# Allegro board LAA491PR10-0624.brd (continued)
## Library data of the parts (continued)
C1-C13 C21-C26 C28-C38 C46-C58 C61-C64 C67-C69 C71 C73 C75-C77 C79-C81 C83 C85 C87-C92 C94-C96 C411 C2326 C2327 C5212 CA21 CA22 CA24 CA25 CA29-CA33 CA38-CA40 CA51 CA54 CA56 CA58 CA60 CA65 CA69 CC14 CC15 CC23 CC25 CC27-CC35 CC40 CD31 CD63 CD64 CE5 CE6 CE11 CE12 CE15 CE18-CE20 CE23 CE24 CE26-CE36 CG1-CG4 CG7-CG11 CI2-CI4 CI7 CI9-CI11 CI13-CI17 CI19 CI22 CI24-CI26 CI30 CI32 CL15 CL19 CL20 CL22 CL26 CL30 CL31 CL34-CL37 CL39 CL41 CL42 CM40 CM44 CM46-CM49 CR1 CR3-CR7 CR9-CR11 CS5 CS6 CS8-CS11 CS13-CS15 CS17 CS105 CS106 CS108 CS109 CV8-CV40 CV43-CV50 CV59-CV76 CV78 CV79 CV81 CV83-CV85 CV87-CV89 CV92-CV95 CV108 CV109 CV112-CV115 CV118 CV119 CV121 CV122 CV124-CV130 CV132 CV133 CV141-CV150 CV152-CV156 CV171-CV174 CV188-CV190 CV193-CV196 CV198 CV199 CV201-CV212 CV216-CV224 CV280 CV281 CV283-CV288 CV290-CV299 CV301-CV308 CV310-CV313 CV315 CV316 CV318 CV319 CV325 CV326 CV328-CV333 CV335 CV349-CV356 CV368-CV401 CX1 CX2 CX4 CX6 CX9-CX11 CX31-CX34 CX37-CX44 CX46 CX47 PC1-PC5 PC7 PC8 PC13-PC16 PC102 PC104 PC108 PC110 PC113 PC114 PC201-PC203 PC207 PC208 PC210 PC300 PC303 PC304 PC307 PC401 PC403 PC404 PC501 PC502 PC504 PC506 PC507 PC509-PC514 PC519-PC523 PC601 PC603 PC604 PC702 PC705 PC708 PC711 PC715 PC717 PC719 PC720 PC722 PC723 PC806 PC809 PC813 PC814 PC816-PC821 PC831 PC832 PC840-PC866 PC869 PC871-PC873 PC1001 PC1003 PC1004 PC1100 PC1101 PC1104 PC1106 PC1200 PC1203 PC1209 PC1214 PC1302 PC1304 PC1306 PC1307 = C_0402
C20 C27 C39-C45 C60 C66 C72 C74 C78 C82 C93 C2305 C2306 C2308 C2309 C2311-C2314 C2316 C2318 C2322-C2324 CA1 CA2 CA23 CA53 CA55 CA57 CA59 CA61-CA64 CA67 CA68 CA71 CA74 CC26 CD59 CD62 CE22 CE25 CG6 CI40 CI43 CI44 CL38 CL43 CL44 CM43 CM45 CR2 CR8 CS16 CV1 CV3-CV7 CV41 CV42 CV77 CV80 CV82 CV86 CV91 CV101-CV103 CV110 CV111 CV116 CV117 CV120 CV123 CV131 CV134 CV136-CV140 CV151 CV170 CV187 CV197 CV200 CV213-CV215 CV322-CV324 CX5 CX35 CX45 PC100 PC103 PC105 PC106 PC109 PC111 PC200 PC204 PC209 PC301 PC302 PC312 PC313 PC503 PC505 PC508 PC701 PC706 PC707 PC709 PC710 PC721 PC803 PC807 PC810 PC811 PC815 PC835 PC867 PC868 PC870 PC1103 PC1105 PC1205 PC1210 PC1212 PC1213 = C_0603
C59 C65 C70 C84 C86 CL33 = C_1206
C2307 C2310 CE16 CG5 CI6 CI12 CI18 CI21 CI23 CI27 CI31 CS7 CS12 CV97 CX3 CX7 CX8 CX36 CX48 PC112 PC115 PC205 PC206 PC211 PC212 PC305 PC306 PC308-PC311 PC400 PC402 PC405 PC517 PC518 PC600 PC602 PC605 PC703 PC704 PC712-PC714 PC716 PC718 PC804 PC805 PC808 PC901-PC923 PC1002 PC1005 PC1102 PC1201 PC1202 PC1204 PC1206 PC1207 PC1211 PC1300 PC1301 PC1303 PC1305 PC1308 = C_0805
CC1-CC11 CC13 CC16-CC22 CC24 = C_0402: room: CPU
CD1-CD11 CD21-CD27 CD30 CD32-CD42 CD52-CD57 CD60 CD61 = C_0402: room: MEMORY
CD12-CD14 CD16-CD20 CD28 CD29 CD43-CD50 CD58 = C_0603: room: MEMORY
CD15 CD51 = C_D2: room: MEMORY
CE1 CE2 = C_0402: room: EDP
CE7-CE9 = C_0402: room: DOCK
CI1 CI8 CI20 PC101 PC107 PC213 PC1108 = C_APXK6R3ARA221MF451
CMOS1 ME1 = SHORTPADS: User Part Number: PART#; room: CPU
CRTF1 = F_1812
CV135 = C_B2
CV327 = C_D2
DA8 = BAT54C-7-F_SOT23-3
DA10 DA12 = AZ5125-02SPR7G_SOT23-3
DC1 = BAT54CW_SOT323-3
DE1 PD101 = L03ESDL5V0CG3-2_SOT-523-3
DE2 = BAT1000-7-F_SOT23-3
DE3-DE5 = PESD5V0U2BT_SOT23-3
DH1 DX1 PD701 = RB751V-40_SOD323-2
DI1 DI4 = IP4292CZ10-TBR_XSON10_2P5X1
DI2 DI5 DI7 = L30ESDL5V0C3-2_SOT23-3
FD1-FD4 = FIDUCIAL_C40M80: room: LED
H2 H4 H5 H8 H9 H12 H16 H17 = H_2P8: room: LED
H6 H10 = H_3P3: room: LED
H7 H18 = H_3P3
H11 = H_2P8
H31-H34 = H_3P7
H35 = H_3P7X3P2N
J9 JP3 JP8 JP9 JP12 PJP203 = JUMP_43X39
J510 J511 J513 JP7 JP13 PJP400 PJP401 PJP600 PJP601 PJP1000 PJP1001 PJP1300 PJP1301 = JUMP_43X79
JCRT1 = C-K_80443B-5K1-152_15P-T
JDB = JESS_UCNR2210M008-0_8P
JDIMM1 JDIMM2 = LCN_DAN06-K4406-0102_204P: room: MEMORY
JFAN = ACES_85204-0300N_3P
JHDD = SANTA_193202-1_22P
JHP = SINGA_2SJ3080-000111F_6P-T
JKB = HB_A823020-SBHR21_30P
JLAN = SANTA_130456-311_8P
JLVDS = STARC_107K40-000001-G2_40P
JMINI = CONCR_525B01BE17A_52P
JODD = SANTA_202801-1_13P
JPWR = HB_A090420-SAHR21_4P
JREAD = T-SOL_143-2300302602_22P_RV
JRTC = LOTES_AAA-BAT-054-K01_2P
JSPK = E-T_3703-Q04N-11R_4P
JTOUCH = ACES_88460-00601-P01_6P
JTP = PS_HPF10052-06M000R_6P
JUSB1 JUSB2 = ACON_TARA4-9K1311_9P: room: ETY-ROOM
JUSB3 = ACON_UARBG-4K1926_4P
JXDP1 = SAMTE_BSH-030-01-L-D-A_60P: room: CPU
L1-L5 = MURAT_LQM2MPN2R2NG0L_2P
L6 L8 L9 = MURAT_BLM18BD102SN1D_L0603_2P
L10-L12 LA3-LA6 PR200 PR206 PR405 PR516 PR519 PR536 PR605 PR709 PR822 PR1101 R3 R4 R23 R245 R2314 R2315 RL19 RL20 RL39 RL40 RV234 RX28 RX29 = R_0603
LA1 = MURAT_BLM15BB221SN1D_2P
LA7-LA10 = KC_FBMA-L10-160808-800LMT_2P
LE1 = KC_FBMA-L11-160808-800LMT_2P: room: EDP
LE2 LV21 LV23 = KC_FBMA-L11-160808-800LMT_2P
LED1 = LED_12-21C-T3D-CM2P1B18X-2C_3P: room: LED
LED2 LED4 = LED_12-21C-T3D-CM2P1B18X-2C_3P
LED3 = LED_HT-210UD5-BP5_3P
LI1 LI3 LI4 LI6 = MURAT_DLW21SN670HQ2L_4P
LI2 LI5 LI7 LI10 LR2 LX6 = KC_WCM-2012HS-900T_4P
LV12-LV16 LV19 LV20 LV22 LV25 LV26 PH1 PH501 PH502 PH800 PR1-PR4 PR6-PR10 PR15-PR18 PR20 PR23 PR24 PR26-PR33 PR102-PR109 PR111 PR114 PR204 PR205 PR207 PR208 PR301 PR304-PR308 PR402-PR404 PR501-PR510 PR512-PR515 PR517 PR518 PR524 PR526 PR528-PR533 PR540 PR602-PR604 PR701 PR703 PR706 PR707 PR711-PR713 PR721 PR723 PR724 PR808 PR813 PR815-PR821 PR824-PR829 PR833-PR840 PR842 PR1001-PR1004 PR1102 PR1105 PR1107 PR1108 PR1110 PR1201-PR1204 PR1208 PR1209 PR1211-PR1214 PR1300-PR1302 PR1304 R1 R2 R6 R10 R12 R13 R15-R22 R24-R42 R159 R250 R252-R256 R286 R2313 R2318 R2329-R2338 R2341 R2346-R2352 R2354-R2359 RA1-RA3 RA5-RA9 RA19 RA51 RA53 RA55 RA56 RA79-RA84 RA130 RA153 RA165 RA166 RA1109 RC10 RC11 RC13 RC21 RC32 RC37 RC56 RC62 RC63 RC65 RC66 RC68 RC75 RC77 RC78 RC89 RC98-RC100 RC105 RC112 RC113 RC123 RC124 RC127-RC132 RC135 RC139 RC362 RD12-RD18 RD45-RD52 RE1-RE3 RE7-RE12 RE18 RE36 RE43 RE47 RE49 RE50 RE60 RE71 RE326 RG1-RG8 RL27 RL31 RL33-RL35 RL37 RL38 RM11 RM13 RM110 RR1-RR3 RS6-RS8 RV1-RV17 RV19-RV49 RV64 RV66-RV71 RV73-RV76 RV81-RV85 RV89-RV91 RV93 RV95-RV98 RV105 RV107-RV109 RV122 RV123 RV125 RV127 RV133 RV136-RV149 RV162 RV163 RV169 RV171 RV181 RV183-RV186 RV191-RV199 RV201-RV204 RV206 RV207 RV215 RV235-RV247 RV250-RV252 RX1-RX3 RX5 RX6 RX8 RX9 RX18 RX21-RX26 RX30 RX31 RX33 RX35-RX53 RX168-RX171 = R_0402
LV17 LV18 = CHENG_MBK1608121YZF_2P
LX1 LX7 LX8 = KC_FBMA-L11-201209-221LMA30_2P
LX9 = CYNTE_PG031B-4R7MS_2P
PBATT = SUYIN_200028MR009G502ZL_9P
PC515 PC516 PC724 = C_EEEFZ1E101P
PC836-PC839 = C_D1
PD1 = IP4223CZ6_SO6
PD2 PD3 = TVNST52302AB0_SOT523-3
PJP100-PJP103 PJP200 PJP201 PJP300 PJP1100 PJP1101 PJP1200 = JUMP_43X118
PJPDC = ACES_50299-00501-003_5P
PL1 PL2 PL4 = CHT_C8BBPH853025_2P
PL3 = CHENG_SMB3025500YA_2P
PL100 PL101 PL1300 = VISHAY_IHLP-2525CZ-01_2P
PL102 PL702 = CYNTE_PCMB053T-1R0MS_2P
PL200 = TAI-T_VMPI0703AR-1R0M-Z01_2P
PL201 PL302 PL501 PL800 PL1201 = L_1812-1806
PL301 PL1200 = CYNTE_PCMB063T-1R0MS_2P
PL400 PL600 = TAIYO_NRS4018T1R0NDGJ_2P
PL502 = TOKO_FDUE1040J-H-R36M-P3_4P
PL701 = TOKO_FDVE1040-H-2R2M-P3_2P
PL802 = MAG_MMD-12CE-R36M-M1L_2P
PL1100 = TAI-T_HCB2012KF-121T50_2P
PL1101 = PANAS_ETQP3W2R2WFN_2P
PQ1-PQ3 = 2N7002DW-T-R7_SOT363-6
PQ4 PQ706 PQ708 = SSM3K7002FU_SC70-3
PQ5 = RHU002N06_SOT323-3
PQ6 = FDV301N_NL_SOT23-3
PQ101-PQ104 PQ200 PQ201 PQ1100 PQ1101 = SIS412DN-T1-GE3_POWERPAK8-5
PQ701 = CSD87312Q3E_SON8-4
PQ702 = AO4407AL_SO8
PQ703 PQ704 = MDU1516URH_POWERDFN56-8-5
PQ705 = MDU1511RH_POWERDFN56-8-5
PQ800 PQ803 = SIR472DP-T1-GE3_POWERPAK8-5
PQ801 PQ802 = SIR818DP-T1_POWERPAK-SO8-5
PQ1201 = 2N7002W-T-R7_SOT323-3
PR5 PR112 PR113 PR203 PR302 PR534 PR705 PR720 PR722 PR805 PR1104 PR1207 PR1303 RE4 = R_1206
PR100 PR101 PR201 PR202 PR300 PR401 PR522 PR535 PR601 PR704 PR708 PR710 PR714 PR715 PR717 PR803 PR804 PR806 PR807 PR809-PR812 PR830 PR845 PR846 PR1103 PR1206 PR1210 R248 R251 R257 R265 R416 RA4 RC57 RC59 RC141 RE37 RE44 RV118-RV121 RV124 RV126 RV248 RX7 RX19 RX20 = R0402_0OHM
PR303 PR802 PR814 PR823 PR1200 R264 RA29-RA32 RC126 RV54 RV59 RX27 = R0603_0OHM
PR702 PR716 = R_1206_4P-D
PU100 = TPS51225CRUKR_QFN20_3X3
PU200 = RT8207MZQW_WQFN20_3X3
PU300 PU1200 = SY8206DQNC_QFN10_3X3
PU400 PU600 = SY8003DFC_DFN8_2X2
PU501 = TPS51622RSM_QFN32_4X4
PU502 = CSD97374CQ4M_SON8_3P5X4P5-S
PU701 = BQ24738RGRR_QFN20_3P5X3P5
PU800 = ISL62881HRZ-T_QFN28_4X4
PU1000 = APL5930KAI-TRG_SO8
PU1100 = TPS51212DSCR_SON10_3X3
PU1300 = SY8036DBC_DFN10_3X3
Q1 Q3 Q4 Q8 Q2307 Q2308 QC3 QD18-QD20 QM30 QV24 QV25 QV28 = 2N7002K_SOT23-3
Q2 QA5 QA6 QH1 QV14 QV15 QX6 = DMN66D0LDW-7_SOT363-6
Q25 = DMG2301U-7_SOT23-3
QC1 = DMN66D0LDW-7_SOT363-6: room: CPU
QD2 = BSS138-G_SOT23-3
QS2 = SI3456BDV-T1-E3_TSOP6
QS3 QX1 = 2N7002KW_SOT323-3
QV22 = AP2301GN-HF_SOT23-3
QX2 = SI3457CDV-T1-GE3_TSOP6
R267 RM25 RM26 RX4 = R0805_0OHM
RC1-RC9 RC12 RC14-RC20 RC22-RC25 RC27-RC29 RC31 RC34-RC36 RC48-RC52 RC58 RC60 RC64 RC67 RC69-RC74 RC76 RC84 RC87 RC88 RC90 RC91 RC97 RC101 RC102 RC104 RC106-RC108 RC110 RC111 RC116 RC118-RC122 RC125 RC133 RC134 RC138 RC140 RC163 = R_0402: room: CPU
RC26 RC33 RC41-RC46 RC81 = R0402_0OHM: room: CPU
RD1 RD4 RD5 RD8 RD10 = R0402_0OHM: room: MEMORY
RD3 RD6 RD7 = R_0402: room: MEMORY
RE5 = R_0402: room: DOCK
RP1 RP36 RP37 RP39-RP57 RP60 = RP_0804_8P4R
RV103 = R_0805
SW1 SW2 = SW_SMT1-05-A_4P
T1 T2 T38-T51 T53 T55 T56 T58 T59 T78-T91 T95 T96 T102 T103 T105 T111-T114 T116 T117 T119 T120 T124-T127 T129-T186 = TPC12
T94 = TPC12: room: LOM
T97-T99 T104 T106 T107 T115 T118 T121 = TPC12: room: SIO
T128 = TPC12: room: KBC
TL2 = TAIMA_IH-115-F_24P
U1 U2 = P_M74VHC1GT125DF2G_SC70_5P
U4 = IT6511FN_QFN56_7X7
U2301 U2304 = TPS22966DPUR_SON14_2X3
U2302 = W25Q64FVSSIG_SO8
U2303 = 74AUP1G07GW_TSSOP5
UA1 = ALC3221-CG_MQFN48_6X6
UC1 = HASWELL-MCP-E-ULT_BGA_1168P-T: room: CPU
UC3 = MC74VHC1G08DFT2G_SC70-5: room: CPU
UC4 = 74CBTLV3126BQ_DHVQFN14_2P5X3: room: CPU
UD1 UV13 UX2 = MC74VHC1G08DFT2G_SC70-5
UE1 = KB9012QF-A2_LQFP128_14X14
UE2 = SN74LVC1G06DCKR_SC70-5
UE3 = G993P1UF_SOP8
UG1 = SLG3NB274VTR_TQFN16_2X3
UI2-UI5 = AP2301MPG-13_MSOP8
UL1 = RTL8106E-CG_QFN32_4X4
UL2 UX1 = APL3512ABI-TRG_SOT23-5
UR1 = RTS5179-GR_QFN24_4X4
UV1 = 2160809000A11SEYMOU_FCBGA_962P
UV3-UV10 = K4G20325FC-HC05_FBGA_170P
UV14 = ADM1032ARMZ-2REEL_MSOP8
UX4 = RTD2136R-CG_QFN48_6X6
X1 = Y_7V27000050_4P
YC1 = Y_Q13FC1350000_2P: room: CPU
YC2 = Y_X3G024000DC1H_4P: room: CPU
YG1 YL2 = Y_FSX3M-25PM20FDO_4P
YV1 = Y_7V27000011_4P

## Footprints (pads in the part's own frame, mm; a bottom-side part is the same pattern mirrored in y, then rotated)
2N7002DW-T-R7_SOT363-6
  oval 0.381x1.397 smd: 1(0,0) 2(0.65,0) 3(1.3,0) 4(1.3,1.725) 5(0.65,1.725) 6(0,1.725)
2N7002K_SOT23-3
  oval 1.016x1.524 smd: 1(0,0) 2(0.965,2.083) 3(-0.965,2.083)
2N7002KW_SOT323-3
  oval 0.813x0.914 smd: 1(0,0) 2(0.65,1.6) 3(-0.65,1.6)
2N7002W-T-R7_SOT323-3
  oval 0.813x0.914 smd: 1(0,0) 2(0.65,1.6) 3(-0.65,1.6)
74AUP1G07GW_TSSOP5
  oval 0.381x1.346 smd: 1(0,0) 2(0.65,0) 3(1.3,0) 4(1.3,1.79) 5(0,1.79)
74CBTLV3126BQ_DHVQFN14_2P5X3
  oval 1.041x0.254 smd: 1(0,0) 7(2.95,0) 8(2.95,0.5) 14(0,0.5)
  oval 0.254x1.041 smd: 2(0.475,-0.975) 3(0.975,-0.975) 4(1.475,-0.975) 5(1.975,-0.975) 6(2.475,-0.975) 9(2.475,1.475) 10(1.975,1.475) 11(1.475,1.475) 12(0.975,1.475) 13(0.475,1.475)
  rect 1.499x0.991 smd: 15(1.475,0.25)
2160809000A11SEYMOU_FCBGA_962P
  round 0.508 smd: A3(0.8,0) A37(26.8,0) A39(27.6,0) AA9(4.8,-15) AA10(5.6,-15) AA11(6.4,-14.4) AA12(7.4,-14.4) AA13(8.4,-14.4) AA15(9.4,-14.4) AA16(10.4,-14.4) AA17(11.4,-14.4) AA18(12.4,-14.4) AA20(13.4,-14.4) AA21(14.4,-14.4) AA22(15.4,-14.4) AA23(16.4,-14.4) AA24(17.4,-14.4) AA26(18.4,-14.4) AA27(19.4,-14.4) AA28(20.4,-14.4) AA29(21.2,-15) AA30(22,-15) AA31(22.8,-15) AB11(6.4,-15.4) AB12(7.4,-15.4) AB13(8.4,-15.4) AB15(9.4,-15.4) AB16(10.4,-15.4) AB17(11.4,-15.4) AB18(12.4,-15.4) AB20(13.4,-15.4) AB21(14.4,-15.4) AB22(15.4,-15.4) AB23(16.4,-15.4) AB24(17.4,-15.4) AB26(18.4,-15.4) AB27(19.4,-15.4) AB28(20.4,-15.4) AC10(5.6,-16.2) AC11(6.4,-16.4) AC12(7.4,-16.4) AC13(8.4,-16.4) AC15(9.4,-16.4) AC16(10.4,-16.4) AC17(11.4,-16.4) AC18(12.4,-16.4) AC20(13.4,-16.4) AC21(14.4,-16.4) AC22(15.4,-16.4) AC23(16.4,-16.4) AC24(17.4,-16.4) AC26(18.4,-16.4) AC27(19.4,-16.4) AC28(20.4,-16.4) AC29(21.2,-16.2) AC30(22,-16.2) AD11(6.4,-17.4) AD12(7.4,-17.4) AD13(8.4,-17.4) AD15(9.4,-17.4) AD16(10.4,-17.4) AD17(11.4,-17.4) AD18(12.4,-17.4) AD20(13.4,-17.4) AD21(14.4,-17.4) AD22(15.4,-17.4) AD23(16.4,-17.4) AD24(17.4,-17.4) AD26(18.4,-17.4) AD27(19.4,-17.4) AD28(20.4,-17.4) AD29(21.2,-17.4) AF12(7.4,-18.4) AF13(8.4,-18.4) AF15(9.4,-18.4) AF16(10.4,-18.4) AF17(11.4,-18.4) AF18(12.4,-18.4) AF20(13.4,-18.4) AF21(14.4,-18.4) AF22(15.4,-18.4) AF23(16.4,-18.4) AF24(17.4,-18.4) AF26(18.4,-18.4) AF27(19.4,-18.4) AF28(20.4,-18.4) AG13(8.4,-19.4) AG15(9.4,-19.4) AG16(10.4,-19.4) AG17(11.4,-19.4) AG18(12.4,-19.4) AG20(13.4,-19.4) AG21(14.4,-19.4) AG22(15.4,-19.4) AG23(16.4,-19.4) AG24(17.4,-19.4) AG26(18.4,-19.4) AG27(19.4,-19.4) AH15(9.4,-20.4) AH16(10.4,-20.4) AH17(11.4,-20.4) AH18(12.4,-20.4) AH20(13.4,-20.4) AH21(14.4,-20.4) AH22(15.4,-20.4) AH23(16.4,-20.4) AH24(17.4,-20.4) AH26(18.4,-20.4) AJ16(10.2,-21.2) AJ17(11.4,-21.2) AJ19(12.6,-21.2) AJ20(13.8,-21.2) AJ21(15,-21.2) AJ23(16.2,-21.2) AJ24(17.4,-21.2) AK17(11.4,-22) AK19(12.6,-22) AK20(13.8,-22) AK21(15,-22) AK23(16.2,-22) AL19(12.6,-22.8) AL20(13.8,-22.8) AL21(15,-22.8) AM20(13.8,-23.6) AU1(0,-26.8) AU3(0.8,-26.8) AU37(26.8,-26.8) AU39(27.6,-26.8) AW1(0,-27.6) AW3(0.8,-27.6) AW37(26.8,-27.6) AW39(27.6,-27.6) C1(0,-0.8) C3(0.8,-0.8) C37(26.8,-0.8) C39(27.6,-0.8) H20(13.8,-4) J19(12.6,-4.8) J20(13.8,-4.8) J21(15,-4.8) K17(11.4,-5.6) K19(12.6,-5.6) K20(13.8,-5.6) K21(15,-5.6) K23(16.2,-5.6) L16(10.4,-6.4) L17(11.4,-6.4) L18(12.4,-6.4) L20(13.4,-6.4) L21(14.4,-6.4) L22(15.4,-6.4) L23(16.4,-6.4) L24(17.4,-6.4) M15(9.4,-7.4) M16(10.4,-7.4) M17(11.4,-7.4) M18(12.4,-7.4) M20(13.4,-7.4) M21(14.4,-7.4) M22(15.4,-7.4) M23(16.4,-7.4) M24(17.4,-7.4) M26(18.4,-7.4) N13(8.4,-8.4) N15(9.4,-8.4) N16(10.4,-8.4) N17(11.4,-8.4) N18(12.4,-8.4) N20(13.4,-8.4) N21(14.4,-8.4) N22(15.4,-8.4) N23(16.4,-8.4) N24(17.4,-8.4) N26(18.4,-8.4) N27(19.4,-8.4) R12(7.4,-9.4) R13(8.4,-9.4) R15(9.4,-9.4) R16(10.4,-9.4) R17(11.4,-9.4) R18(12.4,-9.4) R20(13.4,-9.4) R21(14.4,-9.4) R22(15.4,-9.4) R23(16.4,-9.4) R24(17.4,-9.4) R26(18.4,-9.4) R27(19.4,-9.4) R28(20.4,-9.4) T11(6.4,-10.4) T12(7.4,-10.4) T13(8.4,-10.4) T15(9.4,-10.4) T16(10.4,-10.4) T17(11.4,-10.4) T18(12.4,-10.4) T20(13.4,-10.4) T21(14.4,-10.4) T22(15.4,-10.4) T23(16.4,-10.4) T24(17.4,-10.4) T26(18.4,-10.4) T27(19.4,-10.4) T28(20.4,-10.4) T29(21.2,-10.2) U10(5.6,-11.4) U11(6.4,-11.4) U12(7.4,-11.4) U13(8.4,-11.4) U15(9.4,-11.4) U16(10.4,-11.4) U17(11.4,-11.4) U18(12.4,-11.4) U20(13.4,-11.4) U21(14.4,-11.4) U22(15.4,-11.4) U23(16.4,-11.4) U24(17.4,-11.4) U26(18.4,-11.4) U27(19.4,-11.4) U28(20.4,-11.4) U29(21.2,-11.4) U30(22,-11.4) V11(6.4,-12.4) V12(7.4,-12.4) V13(8.4,-12.4) V15(9.4,-12.4) V16(10.4,-12.4) V17(11.4,-12.4) V18(12.4,-12.4) V20(13.4,-12.4) V21(14.4,-12.4) V22(15.4,-12.4) V23(16.4,-12.4) V24(17.4,-12.4) V26(18.4,-12.4) V27(19.4,-12.4) V28(20.4,-12.4) W9(4.8,-12.6) W10(5.6,-12.6) W29(21.2,-12.6) W30(22,-12.6) W31(22.8,-12.6) Y8(4,-13.8) Y9(4.8,-13.8) Y10(5.6,-13.8) Y11(6.4,-13.4) Y12(7.4,-13.4) Y13(8.4,-13.4) Y15(9.4,-13.4) Y16(10.4,-13.4) Y17(11.4,-13.4) Y18(12.4,-13.4) Y20(13.4,-13.4) Y21(14.4,-13.4) Y22(15.4,-13.4) Y23(16.4,-13.4) Y24(17.4,-13.4) Y26(18.4,-13.4) Y27(19.4,-13.4) Y28(20.4,-13.4) Y29(21.2,-13.8) Y30(22,-13.8) Y31(22.8,-13.8) Y32(23.6,-13.8)
  round 0.305 smd: A5(1.7,0) A6(2.6,0) A8(4.2,0) A10(5.8,0) A12(7.4,0) A14(9,0) A16(10.6,0) A18(12.2,0) A20(13.8,0) A22(15.4,0) A24(17,0) A26(18.6,0) A28(20.2,0) A30(21.8,0) A32(23.4,0) A34(25,0) A35(25.9,0) AA2(0.4,-14.6) AA4(1.2,-14.6) AA6(2.4,-14.8) AA34(25.2,-14.8) AA36(26.4,-14.6) AA38(27.2,-14.6) AB1(0,-15.4) AB3(0.8,-15.4) AB5(1.6,-15.4) AB6(2.4,-15.6) AB34(25.2,-15.6) AB35(26,-15.4) AB37(26.8,-15.4) AB39(27.6,-15.4) AC2(0.4,-16.2) AC4(1.2,-16.2) AC6(2.4,-16.4) AC34(25.2,-16.4) AC36(26.4,-16.2) AC38(27.2,-16.2) AD1(0,-17) AD3(0.8,-17) AD5(1.6,-17) AD6(2.4,-17.2) AD34(25.2,-17.2) AD35(26,-17) AD37(26.8,-17) AD39(27.6,-17) AE2(0.4,-17.8) AE4(1.2,-17.8) AE6(2.4,-18) AE34(25.2,-18) AE36(26.4,-17.8) AE38(27.2,-17.8) AF1(0,-18.6) AF3(0.8,-18.6) AF5(1.6,-18.6) AF6(2.4,-18.8) AF34(25.2,-18.8) AF35(26,-18.6) AF37(26.8,-18.6) AF39(27.6,-18.6) AG2(0.4,-19.4) AG4(1.2,-19.4) AG6(2.4,-19.6) AG34(25.2,-19.6) AG36(26.4,-19.4) AG38(27.2,-19.4) AH1(0,-20.2) AH3(0.8,-20.2) AH5(1.6,-20.2) AH6(2.4,-20.4) AH34(25.2,-20.4) AH35(26,-20.2) AH37(26.8,-20.2) AH39(27.6,-20.2) AJ2(0.4,-21) AJ4(1.2,-21) AJ6(2.4,-21.2) AJ34(25.2,-21.2) AJ36(26.4,-21) AJ38(27.2,-21) AK1(0,-21.8) AK3(0.8,-21.8) AK5(1.6,-21.8) AK6(2.4,-22) AK34(25.2,-22) AK35(26,-21.8) AK37(26.8,-21.8) AK39(27.6,-21.8) AL2(0.4,-22.6) AL4(1.2,-22.6) AL6(2.4,-22.8) AL34(25.2,-22.8) AL36(26.4,-22.6) AL38(27.2,-22.6) AM1(0,-23.4) AM3(0.8,-23.4) AM5(1.6,-23.4) AM6(2.4,-23.6) AM34(25.2,-23.6) AM35(26,-23.4) AM37(26.8,-23.4) AM39(27.6,-23.4) AN2(0.4,-24.2) AN4(1.2,-24.2) AN6(2.4,-24.4) AN34(25.2,-24.4) AN36(26.4,-24.2) AN38(27.2,-24.2) AP1(0,-25) AP3(0.8,-25) AP5(1.6,-25) AP6(2.4,-25.2) AP7(3.2,-25.2) AP8(4,-25.2) AP9(4.8,-25.2) AP10(5.6,-25.2) AP11(6.4,-25.2) AP12(7.2,-25.2) AP13(8,-25.2) AP14(8.8,-25.2) AP15(9.6,-25.2) AP16(10.4,-25.2) AP17(11.2,-25.2) AP18(12,-25.2) AP19(12.8,-25.2) AP20(13.8,-25.2) AP21(14.8,-25.2) AP22(15.6,-25.2) AP23(16.4,-25.2) AP24(17.2,-25.2) AP25(18,-25.2) AP26(18.8,-25.2) AP27(19.6,-25.2) AP28(20.4,-25.2) AP29(21.2,-25.2) AP30(22,-25.2) AP31(22.8,-25.2) AP32(23.6,-25.2) AP33(24.4,-25.2) AP34(25.2,-25.2) AP35(26,-25) AP37(26.8,-25) AP39(27.6,-25) AR1(0,-25.9) AR3(0.8,-25.9) AR5(1.7,-25.9) AR6(2.6,-26) AR8(4.2,-26) AR10(5.8,-26) AR12(7.4,-26) AR14(9,-26) AR16(10.6,-26) AR18(12.2,-26) AR20(13.8,-26) AR22(15.4,-26) AR24(17,-26) AR26(18.6,-26) AR28(20.2,-26) AR30(21.8,-26) AR32(23.4,-26) AR34(25,-26) AR35(25.9,-25.9) AR37(26.8,-25.9) AR39(27.6,-25.9) AT7(3.4,-26.4) AT9(5,-26.4) AT11(6.6,-26.4) AT13(8.2,-26.4) AT15(9.8,-26.4) AT17(11.4,-26.4) AT19(13,-26.4) AT21(14.6,-26.4) AT23(16.2,-26.4) AT25(17.8,-26.4) AT27(19.4,-26.4) AT29(21,-26.4) AT31(22.6,-26.4) AT33(24.2,-26.4) AU5(1.7,-26.8) AU6(2.6,-26.8) AU8(4.2,-26.8) AU10(5.8,-26.8) AU12(7.4,-26.8) AU14(9,-26.8) AU16(10.6,-26.8) AU18(12.2,-26.8) AU20(13.8,-26.8) AU22(15.4,-26.8) AU24(17,-26.8) AU26(18.6,-26.8) AU28(20.2,-26.8) AU30(21.8,-26.8) AU32(23.4,-26.8) AU34(25,-26.8) AU35(25.9,-26.8) AV7(3.4,-27.2) AV9(5,-27.2) AV11(6.6,-27.2) AV13(8.2,-27.2) AV15(9.8,-27.2) AV17(11.4,-27.2) AV19(13,-27.2) AV21(14.6,-27.2) AV23(16.2,-27.2) AV25(17.8,-27.2) AV27(19.4,-27.2) AV29(21,-27.2) AV31(22.6,-27.2) AV33(24.2,-27.2) AW5(1.7,-27.6) AW6(2.6,-27.6) AW8(4.2,-27.6) AW10(5.8,-27.6) AW12(7.4,-27.6) AW14(9,-27.6) AW16(10.6,-27.6) AW18(12.2,-27.6) AW20(13.8,-27.6) AW22(15.4,-27.6) AW24(17,-27.6) AW26(18.6,-27.6) AW28(20.2,-27.6) AW30(21.8,-27.6) AW32(23.4,-27.6) AW34(25,-27.6) AW35(25.9,-27.6) B7(3.4,-0.4) B9(5,-0.4) B11(6.6,-0.4) B13(8.2,-0.4) B15(9.8,-0.4) B17(11.4,-0.4) B19(13,-0.4) B21(14.6,-0.4) B23(16.2,-0.4) B25(17.8,-0.4) B27(19.4,-0.4) B29(21,-0.4) B31(22.6,-0.4) B33(24.2,-0.4) C5(1.7,-0.8) C6(2.6,-0.8) C8(4.2,-0.8) C10(5.8,-0.8) C12(7.4,-0.8) C14(9,-0.8) C16(10.6,-0.8) C18(12.2,-0.8) C20(13.8,-0.8) C22(15.4,-0.8) C24(17,-0.8) C26(18.6,-0.8) C28(20.2,-0.8) C30(21.8,-0.8) C32(23.4,-0.8) C34(25,-0.8) C35(25.9,-0.8) D7(3.4,-1.2) D9(5,-1.2) D11(6.6,-1.2) D13(8.2,-1.2) D15(9.8,-1.2) D17(11.4,-1.2) D19(13,-1.2) D21(14.6,-1.2) D23(16.2,-1.2) D25(17.8,-1.2) D27(19.4,-1.2) D29(21,-1.2) D31(22.6,-1.2) D33(24.2,-1.2) E1(0,-1.7) E3(0.8,-1.7) E5(1.7,-1.7) E6(2.6,-1.6) E8(4.2,-1.6) E10(5.8,-1.6) E12(7.4,-1.6) E14(9,-1.6) E16(10.6,-1.6) E18(12.2,-1.6) E20(13.8,-1.6) E22(15.4,-1.6) E24(17,-1.6) E26(18.6,-1.6) E28(20.2,-1.6) E30(21.8,-1.6) E32(23.4,-1.6) E34(25,-1.6) E35(25.9,-1.7) E37(26.8,-1.7) E39(27.6,-1.7) F1(0,-2.6) F3(0.8,-2.6) F5(1.6,-2.6) F6(2.4,-2.4) F7(3.2,-2.4) F8(4,-2.4) F9(4.8,-2.4) F10(5.6,-2.4) F11(6.4,-2.4) F12(7.2,-2.4) F13(8,-2.4) F14(8.8,-2.4) F15(9.6,-2.4) F16(10.4,-2.4) F17(11.2,-2.4) F18(12,-2.4) F19(12.8,-2.4) F20(13.8,-2.4) F21(14.8,-2.4) F22(15.6,-2.4) F23(16.4,-2.4) F24(17.2,-2.4) F25(18,-2.4) F26(18.8,-2.4) F27(19.6,-2.4) F28(20.4,-2.4) F29(21.2,-2.4) F30(22,-2.4) F31(22.8,-2.4) F32(23.6,-2.4) F33(24.4,-2.4) F34(25.2,-2.4) F35(26,-2.6) F37(26.8,-2.6) F39(27.6,-2.6) G2(0.4,-3.4) G4(1.2,-3.4) G6(2.4,-3.2) G34(25.2,-3.2) G36(26.4,-3.4) G38(27.2,-3.4) H1(0,-4.2) H3(0.8,-4.2) H5(1.6,-4.2) H6(2.4,-4) H34(25.2,-4) H35(26,-4.2) H37(26.8,-4.2) H39(27.6,-4.2) J2(0.4,-5) J4(1.2,-5) J6(2.4,-4.8) J34(25.2,-4.8) J36(26.4,-5) J38(27.2,-5) K1(0,-5.8) K3(0.8,-5.8) K5(1.6,-5.8) K6(2.4,-5.6) K34(25.2,-5.6) K35(26,-5.8) K37(26.8,-5.8) K39(27.6,-5.8) L2(0.4,-6.6) L4(1.2,-6.6) L6(2.4,-6.4) L34(25.2,-6.4) L36(26.4,-6.6) L38(27.2,-6.6) M1(0,-7.4) M3(0.8,-7.4) M5(1.6,-7.4) M6(2.4,-7.2) M34(25.2,-7.2) M35(26,-7.4) M37(26.8,-7.4) M39(27.6,-7.4) N2(0.4,-8.2) N4(1.2,-8.2) N6(2.4,-8) N34(25.2,-8) N36(26.4,-8.2) N38(27.2,-8.2) P1(0,-9) P3(0.8,-9) P5(1.6,-9) P6(2.4,-8.8) P34(25.2,-8.8) P35(26,-9) P37(26.8,-9) P39(27.6,-9) R2(0.4,-9.8) R4(1.2,-9.8) R6(2.4,-9.6) R34(25.2,-9.6) R36(26.4,-9.8) R38(27.2,-9.8) T1(0,-10.6) T3(0.8,-10.6) T5(1.6,-10.6) T6(2.4,-10.4) T34(25.2,-10.4) T35(26,-10.6) T37(26.8,-10.6) T39(27.6,-10.6) U2(0.4,-11.4) U4(1.2,-11.4) U6(2.4,-11.2) U34(25.2,-11.2) U36(26.4,-11.4) U38(27.2,-11.4) V1(0,-12.2) V3(0.8,-12.2) V5(1.6,-12.2) V6(2.4,-12) V34(25.2,-12) V35(26,-12.2) V37(26.8,-12.2) V39(27.6,-12.2) W2(0.4,-13) W4(1.2,-13) W6(2.4,-12.8) W34(25.2,-12.8) W36(26.4,-13) W38(27.2,-13) Y1(0,-13.8) Y3(0.8,-13.8) Y5(1.6,-13.8) Y6(2.4,-13.8) Y34(25.2,-13.8) Y35(26,-13.8) Y37(26.8,-13.8) Y39(27.6,-13.8)
  round 0.406 smd: AA7(3.2,-15) AA8(4,-15) AA32(23.6,-15) AA33(24.4,-15) AC7(3.2,-16.2) AC8(4,-16.2) AC9(4.8,-16.2) AC31(22.8,-16.2) AC32(23.6,-16.2) AC33(24.4,-16.2) AD7(3.2,-17.4) AD8(4,-17.4) AD9(4.8,-17.4) AD10(5.6,-17.4) AD30(22,-17.4) AD31(22.8,-17.4) AD32(23.6,-17.4) AD33(24.4,-17.4) AF7(3.2,-18.6) AF8(4,-18.6) AF9(4.8,-18.6) AF10(5.6,-18.6) AF11(6.4,-18.4) AF29(21.2,-18.6) AF30(22,-18.6) AF31(22.8,-18.6) AF32(23.6,-18.6) AF33(24.4,-18.6) AG7(3.2,-19.8) AG8(4,-19.8) AG9(4.8,-19.8) AG10(5.6,-19.8) AG11(6.4,-19.4) AG12(7.4,-19.4) AG28(20.4,-19.4) AG29(21.2,-19.8) AG30(22,-19.8) AG31(22.8,-19.8) AG32(23.6,-19.8) AG33(24.4,-19.8) AH11(6.4,-20.4) AH12(7.4,-20.4) AH13(8.4,-20.4) AH27(19.4,-20.4) AH28(20.4,-20.4) AH29(21.2,-20.6) AJ7(3.2,-21) AJ8(4,-21) AJ9(4.8,-21) AJ10(5.6,-21) AJ11(6.6,-21.2) AJ13(7.8,-21.2) AJ14(9,-21.2) AJ26(18.6,-21.2) AJ27(19.8,-21.2) AJ28(20.6,-21.2) AJ30(22,-21) AJ31(22.8,-21) AJ32(23.6,-21) AJ33(24.4,-21) AK7(3.2,-22) AK8(4,-22) AK9(4.8,-22) AK10(5.6,-22) AK11(6.6,-22) AK13(7.8,-22) AK14(9,-22) AK16(10.2,-22) AK24(17.4,-22) AK26(18.6,-22) AK27(19.8,-22) AK29(21,-22) AK30(22,-22) AK31(22.8,-22) AK32(23.6,-22) AK33(24.4,-22) AL7(3.2,-22.8) AL8(4,-22.8) AL9(4.8,-22.8) AL10(5.6,-22.8) AL11(6.6,-22.8) AL13(7.8,-22.8) AL14(9,-22.8) AL16(10.2,-22.8) AL17(11.4,-22.8) AL23(16.2,-22.8) AL24(17.4,-22.8) AL26(18.6,-22.8) AL27(19.8,-22.8) AL29(21,-22.8) AL30(22,-22.8) AL31(22.8,-22.8) AL32(23.6,-22.8) AL33(24.4,-22.8) AM7(3.2,-23.6) AM8(4,-23.6) AM9(4.8,-23.6) AM10(5.6,-23.6) AM11(6.6,-23.6) AM13(7.8,-23.6) AM14(9,-23.6) AM16(10.2,-23.6) AM17(11.4,-23.6) AM19(12.6,-23.6) AM21(15,-23.6) AM23(16.2,-23.6) AM24(17.4,-23.6) AM26(18.6,-23.6) AM27(19.8,-23.6) AM29(21,-23.6) AM30(22,-23.6) AM31(22.8,-23.6) AM32(23.6,-23.6) AM33(24.4,-23.6) AN7(3.2,-24.4) AN8(4,-24.4) AN9(4.8,-24.4) AN10(5.6,-24.4) AN11(6.6,-24.4) AN13(7.8,-24.4) AN14(9,-24.4) AN16(10.2,-24.4) AN17(11.4,-24.4) AN19(12.6,-24.4) AN20(13.8,-24.4) AN21(15,-24.4) AN23(16.2,-24.4) AN24(17.4,-24.4) AN26(18.6,-24.4) AN27(19.8,-24.4) AN29(21,-24.4) AN30(22,-24.4) AN31(22.8,-24.4) AN32(23.6,-24.4) AN33(24.4,-24.4) G7(3.2,-3.2) G8(4,-3.2) G9(4.8,-3.2) G10(5.6,-3.2) G11(6.6,-3.2) G13(7.8,-3.2) G14(9,-3.2) G16(10.2,-3.2) G17(11.4,-3.2) G19(12.6,-3.2) G20(13.8,-3.2) G21(15,-3.2) G23(16.2,-3.2) G24(17.4,-3.2) G26(18.6,-3.2) G27(19.8,-3.2) G29(21,-3.2) G30(22,-3.2) G31(22.8,-3.2) G32(23.6,-3.2) G33(24.4,-3.2) H7(3.2,-4) H8(4,-4) H9(4.8,-4) H10(5.6,-4) H11(6.6,-4) H13(7.8,-4) H14(9,-4) H16(10.2,-4) H17(11.4,-4) H19(12.6,-4) H21(15,-4) H23(16.2,-4) H24(17.4,-4) H26(18.6,-4) H27(19.8,-4) H29(21,-4) H30(22,-4) H31(22.8,-4) H32(23.6,-4) H33(24.4,-4) J7(3.2,-4.8) J8(4,-4.8) J9(4.8,-4.8) J10(5.6,-4.8) J11(6.6,-4.8) J13(7.8,-4.8) J14(9,-4.8) J16(10.2,-4.8) J17(11.4,-4.8) J23(16.2,-4.8) J24(17.4,-4.8) J26(18.6,-4.8) J27(19.8,-4.8) J29(21,-4.8) J30(22,-4.8) J31(22.8,-4.8) J32(23.6,-4.8) J33(24.4,-4.8) K7(3.2,-5.6) K8(4,-5.6) K9(4.8,-5.6) K10(5.6,-5.6) K11(6.6,-5.6) K13(7.8,-5.6) K14(9,-5.6) K16(10.2,-5.6) K24(17.4,-5.6) K26(18.6,-5.6) K27(19.8,-5.6) K29(21,-5.6) K30(22,-5.6) K31(22.8,-5.6) K32(23.6,-5.6) K33(24.4,-5.6) L7(3.2,-6.6) L8(4,-6.6) L9(4.8,-6.6) L10(5.6,-6.6) L11(6.4,-6.4) L12(7.4,-6.4) L13(8.4,-6.4) L15(9.4,-6.4) L26(18.4,-6.4) L27(19.4,-6.4) L28(20.4,-6.4) L29(21.2,-6.6) L30(22,-6.6) L31(22.8,-6.6) L32(23.6,-6.6) L33(24.4,-6.6) M11(6.4,-7.4) M12(7.4,-7.4) M13(8.4,-7.4) M27(19.4,-7.4) M28(20.4,-7.4) N7(3.2,-7.8) N8(4,-7.8) N9(4.8,-7.8) N10(5.6,-7.8) N11(6.4,-8.4) N12(7.4,-8.4) N28(20.4,-8.4) N29(21.2,-7.8) N30(22,-7.8) N31(22.8,-7.8) N32(23.6,-7.8) N33(24.4,-7.8) P7(3.2,-9) P8(4,-9) P9(4.8,-9) P10(5.6,-9) P29(21.2,-9) P30(22,-9) P31(22.8,-9) P32(23.6,-9) P33(24.4,-9) R11(6.4,-9.4) T7(3.2,-10.2) T8(4,-10.2) T9(4.8,-10.2) T10(5.6,-10.2) T30(22,-10.2) T31(22.8,-10.2) T32(23.6,-10.2) T33(24.4,-10.2) U7(3.2,-11.4) U8(4,-11.4) U9(4.8,-11.4) U31(22.8,-11.4) U32(23.6,-11.4) U33(24.4,-11.4) W7(3.2,-12.6) W8(4,-12.6) W32(23.6,-12.6) W33(24.4,-12.6) Y7(3.2,-13.8) Y33(24.4,-13.8)
ACES_50299-00501-003_5P
  round 1.803 hole 1.803 unplated: (-0.2,5.2) (8.2,5.2)
  oval 0.889x2.388 smd: 1(0,0) 2(2,0) 3(4,0) 4(6,0) 5(8,0)
ACES_85204-0300N_3P
  oval 0.787x1.6 smd: 1(0,0) 2(1.25,0) 3(2.5,0)
  rect 2.108x2.997 smd: 4(-2.55,-2.9) 5(5.05,-2.9)
ACES_88460-00601-P01_6P
  oval 0.508x0.991 smd: 1(0,0) 2(0.8,0) 3(1.6,0) 4(2.4,0) 5(3.2,0) 6(4,0)
  rect 1.194x1.702 smd: 7(-1.3,-1.95) 8(5.3,-1.95)
ACON_TARA4-9K1311_9P
  round 1.194 hole 0.711: 1(0,0) 2(-2.5,0) 3(-4.5,0) 4(-7,0) 5(-7.5,-1.5) 6(-5.5,-1.5) 7(-3.5,-1.5) 8(-1.5,-1.5) 9(0.5,-1.5)
  oval 1.397x2.591 hole 0.787x2.007: 10(-11.35,-1.59) 13(4.35,-1.59)
  oval 1.397x2.388 hole 0.787x1.803: 11(-11.35,-9.09) 12(4.35,-9.09)
ACON_UARBG-4K1926_4P
  round 1.422 hole 0.914: 1(0,0) 2(-2.5,0) 3(-4.5,0) 4(-7,0)
  oval 1.397x2.819 hole 0.889x2.311: 5(-9.9,0) 6(2.9,0)
  oval 1.219x2.108 hole 0.711x1.6: 7(-11.2,-7.45) 8(4.2,-7.45)
ADM1032ARMZ-2REEL_MSOP8
  oval 0.381x1.626 smd: 1(0,0) 2(0.65,0) 3(1.3,0) 4(1.95,0) 5(1.95,4.3) 6(1.3,4.3) 7(0.65,4.3) 8(0,4.3)
ALC3221-CG_MQFN48_6X6
  oval 0.203x1.041 smd: 1(0,0) 2(0.4,0) 3(0.8,0) 4(1.2,0) 5(1.6,0) 6(2,0) 7(2.4,0) 8(2.8,0) 9(3.2,0) 10(3.6,0) 11(4,0) 12(4.4,0) 25(4.4,5.95) 26(4,5.95) 27(3.6,5.95) 28(3.2,5.95) 29(2.8,5.95) 30(2.4,5.95) 31(2,5.95) 32(1.6,5.95) 33(1.2,5.95) 34(0.8,5.95) 35(0.4,5.95) 36(0,5.95)
  oval 1.041x0.203 smd: 13(5.175,0.775) 14(5.175,1.175) 15(5.175,1.575) 16(5.175,1.975) 17(5.175,2.375) 18(5.175,2.775) 19(5.175,3.175) 20(5.175,3.575) 21(5.175,3.975) 22(5.175,4.375) 23(5.175,4.775) 24(5.175,5.175) 37(-0.775,5.175) 38(-0.775,4.775) 39(-0.775,4.375) 40(-0.775,3.975) 41(-0.775,3.575) 42(-0.775,3.175) 43(-0.775,2.775) 44(-0.775,2.375) 45(-0.775,1.975) 46(-0.775,1.575) 47(-0.775,1.175) 48(-0.775,0.775)
  rect 4.394x4.394 smd: 49(2.2,2.975)
AO4407AL_SO8
  oval 0.635x1.854 smd: 1(0,0) 2(1.27,0) 3(2.54,0) 4(3.81,0) 5(3.81,5.165) 6(2.54,5.165) 7(1.27,5.165) 8(0,5.165)
AP2301GN-HF_SOT23-3
  oval 1.016x1.524 smd: 1(0,0) 2(0.965,2.083) 3(-0.965,2.083)
AP2301MPG-13_MSOP8
  oval 0.381x1.626 smd: 1(0,0) 2(0.65,0) 3(1.3,0) 4(1.95,0) 5(1.95,4.3) 6(1.3,4.3) 7(0.65,4.3) 8(0,4.3)
  rect 1.803x1.499 smd: 9(0.975,2.15)
APL3512ABI-TRG_SOT23-5
  oval 0.61x1.041 smd: 1(0,0) 2(0.95,0) 3(1.9,0) 4(1.9,2.7) 5(0,2.7)
APL5930KAI-TRG_SO8
  oval 0.635x1.854 smd: 1(0,0) 2(1.27,0) 3(2.54,0) 4(3.81,0) 5(3.81,5.165) 6(2.54,5.165) 7(1.27,5.165) 8(0,5.165)
  rect 2.87x2.489 smd: 9(1.905,2.582)
AZ5125-02SPR7G_SOT23-3
  oval 1.016x1.524 smd: 1(0,0) 2(0.965,2.083) 3(-0.965,2.083)
BAT54C-7-F_SOT23-3
  oval 1.016x1.524 smd: 1(0,0) 2(0.965,2.083) 3(-0.965,2.083)
BAT54CW_SOT323-3
  oval 0.66x0.864 smd: 1(0,0) 2(-0.65,-1.85) 3(0.65,-1.85)
BAT1000-7-F_SOT23-3
  oval 1.016x1.524 smd: 1(0,0) 2(0.965,2.083) 3(-0.965,2.083)
BQ24738RGRR_QFN20_3P5X3P5
  oval 0.254x1.041 smd: 1(0,0) 2(0.5,0) 3(1,0) 4(1.5,0) 5(2,0) 11(2,3.45) 12(1.5,3.45) 13(1,3.45) 14(0.5,3.45) 15(0,3.45)
  oval 1.041x0.254 smd: 6(2.725,0.725) 7(2.725,1.225) 8(2.725,1.725) 9(2.725,2.225) 10(2.725,2.725) 16(-0.725,2.725) 17(-0.725,2.225) 18(-0.725,1.725) 19(-0.725,1.225) 20(-0.725,0.725)
  rect 2.057x2.057 smd: 21(1,1.725)
BSS138-G_SOT23-3
  oval 1.016x1.524 smd: 1(0,0) 2(0.965,2.083) 3(-0.965,2.083)
C-K_80443B-5K1-152_15P-T
  round 0.965 hole 0.711: 1(0,0) 2(-2.29,0) 3(-4.58,0) 4(-6.87,0) 5(-9.16,0) 6(1.145,0) 7(-1.145,0) 8(-3.435,0) 9(-5.725,0) 10(-8.015,0) 11(0,-1.4) 12(-2.29,-1.4) 13(-4.58,-1.4) 14(-6.87,-1.4) 15(-9.16,-1.4)
  oval 1.092x2.997 hole 0.787x2.692: 16(5.47,0.1) 17(-14.63,0.1)
C_0402
  rect 0.508x0.559 smd: 1(0,0) 2(0.914,0)
C_0603
  rect 0.635x0.889 smd: 1(0,0) 2(1.397,0)
C_0805
  rect 0.813x1.397 smd: 1(0,0) 2(1.702,0)
C_1206
  rect 1.016x1.651 smd: 1(0,0) 2(2.667,0)
C_APXK6R3ARA221MF451
  oval 3.15x1.6 smd: 1(0,0) 2(5.05,0)
C_B2
  rect 1.346x2.692 smd: 1(0,0) 2(-2.75,0)
C_D1
  rect 1.803x2.794 smd: 1(0,0) 2(6.5,0)
C_D2
  rect 2.388x2.794 smd: 1(0,0) 2(6.4,0)
C_EEEFZ1E101P
  oval 3.2x1.6 smd: 1(0,0) 2(5,0)
CHENG_MBK1608121YZF_2P
  rect 0.991x0.787 smd: 1(0,0) 2(1.6,0)
CHENG_SMB3025500YA_2P
  rect 2.997x1.803 smd: 1(0,0) 2(4,0)
CHT_C8BBPH853025_2P
  rect 2.54x1.397 smd: 1(-3.81,0) 2(3.81,0)
CONCR_525B01BE17A_52P
  round 1.6 hole 1.6 unplated: (-5.075,-4.85) (28.675,-4.85)
  oval 0.61x1.473 hole 0.406x0.711: 1(0,0) 3(0.8,0) 5(1.6,0) 7(2.4,0) 9(3.2,0) 11(4,0) 13(4.8,0) 15(5.6,0) 17(9.6,0) 19(10.4,0) 21(11.2,0) 23(12,0) 25(12.8,0) 27(13.6,0) 29(14.4,0) 31(15.2,0) 33(16,0) 35(16.8,0) 37(17.6,0) 39(18.4,0) 41(19.2,0) 43(20,0) 45(20.8,0) 47(21.6,0) 49(22.4,0) 51(23.2,0)
  oval 0.61x2.007 smd: 2(0.4,2.5) 4(1.2,2.5) 6(2,2.5) 8(2.8,2.5) 10(3.6,2.5) 12(4.4,2.5) 14(5.2,2.5) 16(6,2.5) 18(10,2.5) 20(10.8,2.5) 22(11.6,2.5) 24(12.4,2.5) 26(13.2,2.5) 28(14,2.5) 30(14.8,2.5) 32(15.6,2.5) 34(16.4,2.5) 36(17.2,2.5) 38(18,2.5) 40(18.8,2.5) 42(19.6,2.5) 44(20.4,2.5) 46(21.2,2.5) 48(22,2.5) 50(22.8,2.5) 52(23.6,2.5)
  oval 1.549x2.769 hole 0.787x2.007: 53(28.675,-7.65) 54(-5.075,-7.65)
CSD87312Q3E_SON8-4
  rect 2.388x0.66 smd: 1(0,0)
  rect 0.432x0.66 smd: 2(0.975,2.95)
  rect 1.753x0.66 smd: 3(-0.325,2.95)
  custom 0.475x0.475 smd: 4(0,1.475)
CSD97374CQ4M_SON8_3P5X4P5-S
  oval 0.203x0.914 smd: 1(0,0) 2(0.4,0) 3(0.8,0) 6(0.8,3.505) 7(0.4,3.505) 8(0,3.505)
  custom 0.225x0.225 smd: 4(2.2,0.265) 5(2.2,3.24)
  rect 4.039x2.21 smd: 9(1.6,1.752)
CYNTE_PCMB053T-1R0MS_2P
  rect 1.905x2.794 smd: 1(0,0) 2(4.1,0)
CYNTE_PCMB063T-1R0MS_2P
  rect 2.159x3.505 smd: 1(0,0) 2(5.85,0)
CYNTE_PG031B-4R7MS_2P
  rect 0.889x1.194 smd: 1(0,0) 2(2.2,0)
DMG2301U-7_SOT23-3
  oval 1.016x1.524 smd: 1(0,0) 2(0.965,2.083) 3(-0.965,2.083)
DMN66D0LDW-7_SOT363-6
  oval 0.432x0.61 smd: 1(0,0) 2(0.65,0) 3(1.3,0) 4(1.3,1.9) 5(0.65,1.9) 6(0,1.9)
E-T_3703-Q04N-11R_4P
  oval 0.61x1.549 smd: 1(0,0) 2(1,0) 3(2,0) 4(3,0)
  rect 1.194x2.007 smd: 5(4.3,-3.775) 6(-1.3,-3.775)
F_1812
  rect 1.245x3.658 smd: 1(-2.07,0) 2(2.07,0)
FDV301N_NL_SOT23-3
  oval 1.016x1.524 smd: 1(0,0) 2(0.965,2.083) 3(-0.965,2.083)
FIDUCIAL_C40M80
  round 1.016 smd: 1(0,0)
G993P1UF_SOP8
  oval 0.635x1.854 smd: 1(0,0) 2(1.27,0) 3(2.54,0) 4(3.81,0) 5(3.81,5.165) 6(2.54,5.165) 7(1.27,5.165) 8(0,5.165)
H_2P8
  round 3.302 hole 2.794: 1(0,0)
H_3P3
  round 3.81 hole 3.302: 1(0,0)
H_3P7
  round 4.216 hole 3.708: 1(0,0)
H_3P7X3P2N
  oval 3.708x3.2 hole 3.708x3.2 unplated: (0,0)
HASWELL-MCP-E-ULT_BGA_1168P-T
  round 0.508 smd: A3(-1.137,0) A62(-38.036,0) AW1(0,22.042) AW63(-38.628,22.057) AY2(-0.543,22.628) AY62(-38.062,22.628) B2(-0.508,0.508) B63(-38.628,0.592) C1(0,1.137)
  round 0.381 smd: A4(-1.894,0) A5(-2.554,0) A6(-3.75,0) A59(-35.9,0) A60(-36.726,0) A61(-37.386,0) AA9(-5.032,11.576) AA21(-11.688,11.489) AA23(-13.115,11.489) AA58(-35.377,11.33) AB10(-5.476,12.053) AB20(-11.18,11.896) AB21(-11.688,12.302) AB22(-12.607,11.896) AB23(-13.115,12.302) AB57(-35.057,11.98) AC9(-5.032,12.529) AC20(-11.18,12.709) AC22(-12.607,12.709) AC58(-35.377,12.63) AD10(-5.476,13.005) AD21(-11.688,13.115) AD23(-13.115,13.115) AD57(-35.057,13.28) AE9(-5.032,13.481) AE10(-5.476,13.958) AE20(-11.18,13.521) AE21(-11.688,13.928) AE22(-12.607,13.521) AE23(-13.115,13.928) AE58(-35.377,13.931) AF9(-5.032,14.434) AF11(-6.059,14.282) AF12(-6.872,14.282) AF14(-7.685,14.282) AF15(-8.497,14.282) AF17(-9.31,14.282) AF18(-10.123,14.282) AF20(-10.936,14.282) AF22(-12.607,14.334) AG10(-5.653,14.79) AG11(-6.465,14.79) AG13(-7.278,14.79) AG14(-8.091,14.79) AG16(-8.904,14.79) AG17(-9.717,14.79) AG19(-10.529,14.79) AG20(-11.342,14.79) AG23(-13.115,14.741) AG57(-35.057,14.581) AG58(-35.692,15.009) AH22(-12.607,15.147) AH24(-13.92,15.289) AH26(-15.22,15.289) AH28(-16.521,15.289) AH30(-17.821,15.289) AH32(-19.122,15.289) AH34(-20.422,15.289) AH36(-21.723,15.289) AH38(-23.023,15.289) AH40(-24.324,15.289) AH42(-25.624,15.289) AH44(-26.925,15.289) AH46(-28.225,15.289) AH49(-29.526,15.289) AH51(-30.826,15.289) AH53(-32.127,15.289) AH55(-33.427,15.289) AH57(-34.728,15.289) AJ23(-13.115,15.553) AJ25(-14.57,15.614) AJ27(-15.871,15.614) AJ29(-17.171,15.614) AJ31(-18.472,15.614) AJ33(-19.772,15.614) AJ35(-21.073,15.614) AJ37(-22.373,15.614) AJ39(-23.674,15.614) AJ41(-24.974,15.614) AJ43(-26.275,15.614) AJ45(-27.575,15.614) AJ47(-28.875,15.614) AJ50(-30.176,15.614) AJ52(-31.476,15.614) AJ54(-32.777,15.614) AJ56(-34.077,15.614) AJ58(-35.378,15.614) AT1(0,19.997) AT63(-38.628,19.848) AU1(0,20.657) AU63(-38.628,20.673) AV1(0,21.318) AV2(-0.66,21.308) AV62(-37.978,21.318) AV63(-38.628,21.333) AW2(-0.66,21.968) AW3(-1.321,21.968) AW61(-37.328,21.978) AW62(-37.978,21.978) AY3(-1.267,22.628) AY4(-1.928,22.628) AY5(-2.588,22.628) AY59(-36.088,22.628) AY60(-36.748,22.628) AY61(-37.409,22.628) B3(-1.259,0.65) B61(-37.315,0.66) B62(-37.978,0.724) C2(-0.65,1.259) C62(-37.978,1.384) C63(-38.628,1.316) D1(0,1.861) D63(-38.628,1.976) E1(0,2.522) E23(-13.333,2.601) E25(-14.714,2.601) E27(-15.84,2.601) E29(-17.221,2.601) E31(-18.348,2.601) E33(-19.729,2.601) E35(-20.855,2.601) E37(-22.236,2.601) E39(-23.363,2.601) E41(-24.744,2.601) E43(-25.87,2.601) E45(-27.251,2.601) E47(-28.378,2.601) E49(-29.759,2.601) E51(-30.885,2.601) E53(-32.266,2.601) E55(-33.393,2.601) E57(-34.774,2.601) E63(-38.628,2.647) F1(0,3.436) F22(-12.717,3.058) F24(-14.023,3.126) F26(-15.277,3.126) F28(-16.531,3.126) F30(-17.785,3.126) F32(-19.038,3.126) F34(-20.292,3.126) F36(-21.546,3.126) F38(-22.8,3.126) F40(-24.053,3.126) F42(-25.307,3.126) F44(-26.561,3.126) F46(-27.815,3.126) F48(-29.068,3.126) F50(-30.322,3.126) F52(-31.576,3.126) F54(-32.83,3.126) F56(-34.083,3.126) F58(-35.377,3.126) G22(-12.607,3.768) G23(-13.333,3.451) G25(-14.714,3.451) G27(-15.84,3.451) G29(-17.221,3.451) G31(-18.348,3.451) G33(-19.729,3.451) G35(-20.855,3.451) G37(-22.236,3.451) G39(-23.363,3.451) G41(-24.744,3.451) G43(-25.87,3.451) G45(-27.251,3.451) G47(-28.378,3.451) G49(-29.759,3.451) G51(-30.885,3.451) G53(-32.266,3.451) G55(-33.393,3.451) G57(-34.774,3.451) H22(-12.607,4.581) H23(-13.115,4.174) H57(-35.057,4.101) J22(-12.607,5.393) J23(-13.115,4.987) J58(-35.377,4.827) K9(-5.032,5.861) K10(-5.935,5.7) K12(-6.888,5.7) K14(-7.84,5.7) K16(-8.793,5.7) K18(-9.745,5.7) K19(-10.698,5.7) K21(-11.65,5.7) K23(-13.115,5.8) K57(-35.057,5.478) L10(-5.476,6.338) L11(-6.412,6.144) L13(-7.364,6.144) L15(-8.317,6.144) L17(-9.269,6.144) L18(-10.222,6.144) L20(-11.18,6.206) L22(-12.607,6.206) L58(-35.377,6.128) M9(-5.032,6.814) M20(-11.18,7.019) M21(-11.688,6.613) M22(-12.607,7.019) M23(-13.115,6.613) M57(-35.057,6.778) N10(-5.476,7.29) N21(-11.688,7.425) N23(-13.115,7.425) N58(-35.377,7.428) P9(-5.032,7.766) P20(-11.18,7.832) P22(-12.607,7.832) P57(-35.057,8.078) R10(-5.476,8.243) R20(-11.18,8.645) R21(-11.688,8.238) R22(-12.607,8.645) R23(-13.115,8.238) T9(-5.032,8.719) T21(-11.688,9.051) T23(-13.115,9.051) T58(-35.377,8.729) U9(-5.032,9.671) U10(-5.476,9.195) U20(-11.18,9.457) U22(-12.607,9.457) U57(-35.057,9.379) V10(-5.476,10.148) V21(-11.688,9.864) V23(-13.115,9.864) V58(-35.377,10.029) W9(-5.032,10.624) W20(-11.18,10.27) W21(-11.688,10.677) W22(-12.607,10.27) W23(-13.115,10.677) W57(-35.057,10.679) Y10(-5.476,11.1) Y20(-11.18,11.083) Y22(-12.607,11.083)
  round 0.305 smd: A8(-4.538,0) A9(-5.452,0) A11(-6.367,0) A12(-7.116,0) A14(-8.03,0) A15(-8.945,0) A17(-9.694,0) A18(-10.608,0) A20(-11.523,0) A21(-12.272,0) A23(-13.186,0) A24(-14.023,0.325) A25(-14.714,0) A27(-15.84,0) A28(-16.531,0.325) A29(-17.221,0) A31(-18.348,0) A32(-19.038,0.325) A33(-19.729,0) A35(-20.855,0) A36(-21.546,0.325) A37(-22.236,0) A39(-23.363,0) A40(-24.053,0.325) A41(-24.744,0) A43(-25.87,0) A44(-26.561,0.325) A45(-27.251,0) A47(-28.378,0) A48(-29.068,0.325) A49(-29.759,0) A51(-30.885,0) A52(-31.576,0.325) A53(-32.266,0) A55(-33.393,0) A56(-34.083,0.325) A57(-34.774,0) AA1(0,11.717) AA2(-0.65,11.717) AA3(-1.3,11.678) AA4(-1.951,11.678) AA59(-36.027,11.638) AA60(-36.678,11.638) AA61(-37.328,11.638) AA62(-37.978,11.676) AA63(-38.628,11.676) AB5(-2.637,12.053) AB6(-3.287,12.053) AB7(-3.937,12.053) AB8(-4.587,12.053) AC1(0,12.466) AC2(-0.65,12.466) AC3(-1.3,12.504) AC4(-1.951,12.504) AC59(-36.027,12.464) AC60(-36.678,12.464) AC61(-37.328,12.464) AC62(-37.978,12.426) AC63(-38.628,12.426) AD1(0,13.215) AD2(-0.65,13.215) AD3(-1.3,13.177) AD4(-1.951,13.177) AD5(-2.637,13.005) AD6(-3.287,13.005) AD7(-3.937,13.005) AD8(-4.587,13.005) AD59(-36.027,13.137) AD60(-36.678,13.137) AD61(-37.328,13.137) AD62(-37.978,13.175) AD63(-38.628,13.175) AE5(-2.637,13.958) AE6(-3.287,13.958) AE7(-3.937,13.958) AE8(-4.587,13.958) AE59(-36.027,13.962) AE60(-36.678,13.962) AE61(-37.328,13.962) AE62(-37.978,13.924) AE63(-38.628,13.924) AF1(0,13.964) AF2(-0.65,13.964) AF3(-1.3,14.003) AF4(-1.951,14.003) AG1(0,14.714) AG2(-0.65,14.714) AG3(-1.3,14.676) AG4(-1.951,14.676) AG5(-2.637,14.91) AG6(-3.287,14.91) AG7(-3.937,14.91) AG8(-4.587,14.91) AG21(-11.955,15.122) AG60(-36.352,14.602) AG61(-37.003,14.602) AG62(-37.653,14.602) AG63(-38.303,14.602) AH1(0,15.463) AH2(-0.65,15.463) AH3(-1.3,15.501) AH4(-1.951,15.501) AH10(-5.653,15.476) AH11(-6.465,15.476) AH13(-7.278,15.476) AH14(-8.091,15.476) AH16(-8.904,15.476) AH17(-9.717,15.476) AH19(-10.529,15.476) AH20(-11.342,15.476) AH60(-36.678,15.278) AH61(-37.328,15.278) AH62(-37.978,15.278) AH63(-38.628,15.278) AJ5(-2.637,15.863) AJ6(-3.287,15.863) AJ7(-3.937,15.863) AJ8(-4.587,15.863) AJ10(-5.653,16.126) AJ11(-6.465,16.126) AJ13(-7.278,16.126) AJ14(-8.091,16.126) AJ60(-36.352,15.954) AJ61(-37.003,15.954) AJ62(-37.653,15.954) AJ63(-38.303,15.954) AK1(0,16.212) AK2(-0.65,16.212) AK3(-1.3,16.174) AK4(-1.951,16.174) AK8(-4.303,16.451) AK18(-9.848,16.266) AK20(-10.801,16.266) AK21(-11.753,16.266) AK60(-36.678,16.523) AK61(-37.328,16.523) AK62(-37.978,16.629) AK63(-38.628,16.629) AL1(0,16.962) AL2(-0.65,16.962) AL3(-1.3,17) AL4(-1.951,17) AL5(-2.901,16.776) AL7(-3.739,16.776) AL8(-4.303,17.101) AL10(-5.658,16.776) AL11(-6.221,17.101) AL13(-7.576,16.776) AL15(-8.14,17.101) AL17(-9.222,16.583) AL18(-9.848,16.916) AL20(-10.801,16.916) AL21(-11.753,16.916) AL22(-12.706,16.916) AL23(-13.529,16.916) AL25(-14.504,16.916) AL26(-15.456,16.916) AL28(-16.409,16.916) AL29(-17.361,16.916) AL31(-18.26,16.591) AL32(-18.824,16.916) AL33(-19.726,16.916) AL35(-20.729,16.916) AL36(-21.58,16.916) AL38(-22.634,16.916) AL39(-23.542,16.591) AL40(-24.131,16.916) AL42(-24.944,16.916) AL43(-25.897,16.916) AL45(-26.874,16.916) AL46(-27.802,16.916) AL48(-28.856,16.916) AL49(-29.757,16.916) AL51(-30.761,16.916) AL52(-31.583,16.916) AL54(-32.61,16.916) AL55(-33.562,16.916) AL57(-34.509,16.916) AL58(-35.408,16.916) AL60(-36.352,17.169) AL61(-37.003,17.169) AM1(0,17.711) AM2(-0.65,17.711) AM3(-1.3,17.673) AM4(-1.951,17.673) AM5(-2.901,17.426) AM7(-3.739,17.426) AM8(-4.303,17.752) AM10(-5.658,17.426) AM11(-6.221,17.752) AM13(-7.576,17.426) AM15(-8.14,17.752) AM17(-9.222,17.233) AM18(-9.848,17.567) AM20(-10.801,17.567) AM21(-11.753,17.567) AM22(-12.706,17.567) AM23(-13.529,17.567) AM25(-14.504,17.567) AM26(-15.456,17.567) AM28(-16.409,17.567) AM29(-17.361,17.567) AM31(-18.26,17.242) AM32(-18.824,17.567) AM33(-19.726,17.567) AM35(-20.729,17.567) AM36(-21.58,17.567) AM38(-22.634,17.567) AM40(-24.131,17.567) AM42(-24.944,17.567) AM43(-25.897,17.567) AM45(-26.874,17.567) AM46(-27.802,17.567) AM48(-28.856,17.567) AM49(-29.757,17.567) AM51(-30.761,17.567) AM52(-31.583,17.567) AM54(-32.61,17.567) AM55(-33.562,17.567) AM57(-34.509,17.567) AM58(-35.408,17.567) AM60(-36.678,17.816) AM61(-37.328,17.816) AM62(-37.978,17.709) AM63(-38.628,17.709) AN1(0,18.46) AN2(-0.65,18.46) AN3(-1.3,18.498) AN4(-1.951,18.498) AN5(-2.901,18.077) AN7(-3.739,18.077) AN8(-4.303,18.402) AN10(-5.658,18.077) AN11(-6.221,18.402) AN13(-7.576,18.077) AN15(-8.14,18.402) AN17(-9.222,17.883) AN18(-9.848,18.217) AN20(-10.801,18.217) AN21(-11.753,18.217) AN22(-12.706,18.217) AN23(-13.529,18.217) AN25(-14.504,18.217) AN26(-15.456,18.217) AN28(-16.409,18.217) AN29(-17.361,18.217) AN31(-18.26,17.892) AN32(-18.824,18.217) AN33(-19.726,18.217) AN35(-20.729,18.217) AN36(-21.58,18.217) AN38(-22.634,18.217) AN39(-23.542,17.892) AN40(-24.131,18.217) AN42(-24.944,18.217) AN43(-25.897,18.217) AN45(-26.874,18.217) AN46(-27.802,18.217) AN48(-28.856,18.217) AN49(-29.757,18.217) AN51(-30.761,18.217) AN52(-31.583,18.217) AN54(-32.61,18.217) AN55(-33.562,18.217) AN57(-34.509,18.217) AN58(-35.408,18.217) AN60(-36.352,18.385) AN61(-37.003,18.385) AN62(-37.653,18.385) AN63(-38.303,18.385) AP1(0,19.21) AP2(-0.65,19.21) AP3(-1.3,19.171) AP4(-1.951,19.171) AP5(-2.901,18.727) AP7(-3.739,18.727) AP8(-4.303,19.052) AP10(-5.658,18.727) AP11(-6.221,19.052) AP13(-7.576,18.727) AP15(-8.14,19.052) AP17(-9.222,18.533) AP18(-9.848,18.867) AP20(-10.801,18.867) AP21(-11.753,18.867) AP22(-12.706,18.867) AP23(-13.529,18.867) AP25(-14.504,18.867) AP26(-15.456,18.867) AP28(-16.409,18.867) AP29(-17.361,18.867) AP31(-18.26,18.542) AP32(-18.824,18.867) AP33(-19.726,18.867) AP35(-20.729,18.867) AP36(-21.58,18.867) AP38(-22.634,18.867) AP39(-23.542,18.542) AP40(-24.131,18.867) AP42(-24.944,18.867) AP43(-25.897,18.867) AP45(-26.874,18.867) AP46(-27.802,18.867) AP48(-28.856,18.867) AP49(-29.757,18.867) AP51(-30.761,18.867) AP52(-31.583,18.867) AP54(-32.61,18.867) AP55(-33.562,18.867) AP57(-34.509,18.867) AP58(-35.408,18.867) AP60(-36.678,19.06) AP61(-37.328,19.06) AP62(-37.978,19.06) AP63(-38.628,19.06) AR5(-2.901,19.377) AR7(-3.739,19.377) AR8(-4.303,19.702) AR10(-5.658,19.377) AR11(-6.221,19.702) AR13(-7.576,19.377) AR15(-8.14,19.702) AR17(-9.222,19.184) AR18(-9.848,19.517) AR20(-10.801,19.517) AR21(-11.753,19.517) AR22(-12.706,19.517) AR23(-13.529,19.517) AR25(-14.504,19.517) AR26(-15.456,19.517) AR28(-16.409,19.517) AR29(-17.361,19.517) AR31(-18.26,19.192) AR32(-18.824,19.517) AR33(-19.726,19.517) AR35(-20.729,19.517) AR36(-21.58,19.517) AR38(-22.634,19.517) AR39(-23.542,19.192) AR40(-24.131,19.517) AR42(-24.944,19.517) AR43(-25.897,19.517) AR45(-26.874,19.517) AR46(-27.802,19.517) AR48(-28.856,19.517) AR49(-29.757,19.517) AR51(-30.761,19.517) AR52(-31.583,19.517) AR54(-32.61,19.517) AR55(-33.562,19.517) AR57(-34.509,19.517) AR58(-35.408,19.517) AT2(-0.65,19.959) AT3(-1.3,19.997) AT4(-1.951,19.997) AT5(-2.901,20.027) AT7(-3.739,20.027) AT10(-5.658,20.027) AT13(-7.576,20.027) AT35(-20.437,20.22) AT37(-22.011,20.22) AT40(-23.586,20.22) AT42(-25.161,20.22) AT43(-26.736,20.22) AT46(-28.311,20.22) AT49(-29.912,20.248) AT61(-37.003,19.634) AT62(-37.812,19.69) AU2(-0.655,20.647) AU3(-1.315,20.647) AU4(-1.976,20.647) AU6(-3.337,20.678) AU7(-4.163,20.678) AU8(-4.836,20.678) AU10(-5.661,20.678) AU11(-6.335,20.678) AU12(-7.16,20.678) AU14(-7.833,20.678) AU15(-8.659,20.678) AU16(-9.222,20.353) AU17(-9.86,20.678) AU18(-10.536,20.353) AU19(-11.105,20.678) AU20(-11.751,20.353) AU21(-12.397,20.678) AU22(-12.966,20.353) AU23(-13.642,20.678) AU24(-14.318,20.353) AU25(-14.993,20.678) AU26(-15.669,20.353) AU27(-16.238,20.678) AU28(-16.884,20.353) AU29(-17.531,20.678) AU30(-18.1,20.353) AU31(-18.775,20.678) AU33(-19.372,20.33) AU34(-19.974,20.678) AU35(-20.899,20.678) AU36(-21.549,20.678) AU37(-22.474,20.678) AU39(-23.124,20.678) AU40(-24.048,20.678) AU41(-24.699,20.678) AU42(-25.623,20.678) AU43(-26.274,20.678) AU44(-27.198,20.678) AU46(-27.848,20.678) AU47(-28.773,20.678) AU49(-29.423,20.678) AU50(-30.4,20.678) AU51(-30.98,20.353) AU52(-31.656,20.678) AU53(-32.331,20.353) AU54(-32.9,20.678) AU55(-33.547,20.353) AU56(-34.193,20.678) AU57(-34.762,20.353) AU58(-35.438,20.678) AU59(-36.002,20.353) AU60(-36.566,20.678) AU61(-37.277,20.401) AU62(-37.978,20.663) AV3(-1.321,21.308) AV4(-1.976,21.308) AV5(-2.664,21.328) AV6(-3.337,21.328) AV7(-4.163,21.328) AV8(-4.836,21.328) AV10(-5.661,21.328) AV11(-6.335,21.328) AV12(-7.16,21.328) AV14(-7.833,21.328) AV15(-8.659,21.328) AV16(-9.222,21.003) AV17(-9.86,21.328) AV18(-10.536,21.003) AV19(-11.105,21.328) AV20(-11.751,21.003) AV21(-12.397,21.328) AV22(-12.966,21.003) AV23(-13.642,21.328) AV24(-14.318,21.003) AV25(-14.993,21.328) AV26(-15.669,21.003) AV27(-16.238,21.328) AV28(-16.884,21.003) AV29(-17.531,21.328) AV30(-18.1,21.003) AV31(-18.775,21.328) AV33(-19.4,21.003) AV34(-20.024,21.328) AV35(-20.849,21.328) AV36(-21.599,21.328) AV37(-22.424,21.328) AV39(-23.173,21.328) AV40(-23.999,21.328) AV41(-24.748,21.328) AV42(-25.574,21.328) AV43(-26.323,21.328) AV44(-27.149,21.328) AV46(-27.898,21.328) AV47(-28.723,21.328) AV49(-29.473,21.328) AV50(-30.298,21.328) AV51(-30.98,21.003) AV52(-31.656,21.328) AV53(-32.331,21.003) AV54(-32.9,21.328) AV55(-33.547,21.003) AV56(-34.193,21.328) AV57(-34.762,21.003) AV58(-35.438,21.328) AV59(-36.002,21.003) AV60(-36.566,21.328) AV61(-37.302,21.051) AW4(-1.976,21.968) AW5(-2.626,21.978) AW6(-3.375,21.978) AW7(-4.125,21.978) AW8(-4.874,21.978) AW10(-5.623,21.978) AW11(-6.373,21.978) AW12(-7.122,21.978) AW14(-7.871,21.978) AW15(-8.621,21.978) AW16(-9.222,21.653) AW17(-9.86,21.978) AW18(-10.536,21.653) AW19(-11.211,21.978) AW21(-12.291,21.978) AW22(-12.966,21.653) AW23(-13.642,21.978) AW24(-14.318,21.653) AW25(-14.993,21.978) AW26(-15.669,21.653) AW27(-16.345,21.978) AW29(-17.424,21.978) AW30(-18.1,21.653) AW31(-18.775,21.978) AW33(-19.451,21.653) AW34(-20.024,21.978) AW35(-20.849,21.978) AW36(-21.599,21.978) AW37(-22.424,21.978) AW39(-23.173,21.978) AW40(-23.999,21.978) AW41(-24.748,21.978) AW42(-25.574,21.978) AW43(-26.323,21.978) AW44(-27.149,21.978) AW46(-27.898,21.978) AW47(-28.723,21.978) AW49(-29.473,21.978) AW50(-30.298,21.978) AW51(-30.98,21.653) AW52(-31.656,21.978) AW53(-32.331,21.653) AW54(-33.007,21.978) AW56(-34.087,21.978) AW57(-34.762,21.653) AW58(-35.438,21.978) AW59(-36.002,21.653) AW60(-36.566,21.978) AY6(-3.375,22.628) AY7(-4.125,22.628) AY8(-4.874,22.628) AY10(-5.623,22.628) AY11(-6.373,22.628) AY12(-7.122,22.628) AY14(-7.871,22.628) AY15(-8.621,22.628) AY16(-9.184,22.303) AY17(-9.86,22.628) AY18(-10.536,22.303) AY19(-11.211,22.628) AY21(-12.291,22.628) AY22(-12.966,22.303) AY23(-13.642,22.628) AY24(-14.318,22.303) AY25(-14.993,22.628) AY26(-15.669,22.303) AY27(-16.345,22.628) AY29(-17.424,22.628) AY30(-18.1,22.303) AY31(-18.775,22.628) AY33(-19.451,22.303) AY34(-20.024,22.628) AY35(-20.849,22.628) AY36(-21.599,22.628) AY37(-22.424,22.628) AY39(-23.173,22.628) AY40(-23.999,22.628) AY41(-24.748,22.628) AY42(-25.574,22.628) AY43(-26.323,22.628) AY44(-27.149,22.628) AY46(-27.898,22.628) AY47(-28.723,22.628) AY49(-29.473,22.628) AY50(-30.298,22.628) AY51(-30.98,22.303) AY52(-31.656,22.628) AY53(-32.331,22.303) AY54(-33.007,22.628) AY56(-34.087,22.628) AY57(-34.762,22.303) AY58(-35.438,22.628) B4(-1.922,0.65) B5(-3.138,0.643) B6(-4.119,0.643) B8(-4.891,0.643) B9(-5.716,0.643) B11(-6.697,0.643) B12(-7.469,0.643) B14(-8.294,0.643) B15(-9.275,0.643) B17(-10.047,0.643) B18(-10.872,0.643) B20(-11.853,0.643) B21(-12.272,1.196) B22(-12.625,0.643) B23(-13.451,0.643) B24(-14.023,0.975) B25(-14.714,0.65) B26(-15.277,0.975) B27(-15.84,0.65) B28(-16.531,0.975) B29(-17.221,0.65) B30(-17.785,0.975) B31(-18.348,0.65) B32(-19.038,0.975) B33(-19.729,0.65) B34(-20.292,0.975) B35(-20.855,0.65) B36(-21.546,0.975) B37(-22.236,0.65) B38(-22.8,0.975) B39(-23.363,0.65) B40(-24.053,0.975) B41(-24.744,0.65) B42(-25.307,0.975) B43(-25.87,0.65) B44(-26.561,0.975) B45(-27.251,0.65) B46(-27.815,0.975) B47(-28.378,0.65) B48(-29.068,0.975) B49(-29.759,0.65) B50(-30.322,0.975) B51(-30.885,0.65) B52(-31.576,0.975) B53(-32.266,0.65) B54(-32.83,0.975) B55(-33.393,0.65) B56(-34.083,0.975) B57(-34.774,0.65) B58(-35.337,0.975) B59(-35.9,0.65) B60(-36.665,0.66) C3(-1.302,1.302) C4(-2.118,1.272) C5(-2.772,1.196) C6(-3.776,1.196) C8(-4.538,1.196) C9(-5.351,1.196) C11(-6.354,1.196) C12(-7.116,1.196) C14(-7.929,1.196) C15(-8.932,1.196) C17(-9.694,1.196) C18(-10.507,1.196) C20(-11.51,1.196) C21(-11.891,1.786) C22(-12.678,1.786) C23(-13.085,1.196) C24(-14.051,2.032) C25(-14.714,1.3) C26(-15.277,1.626) C27(-15.84,1.3) C28(-16.558,2.032) C29(-17.221,1.3) C30(-17.785,1.626) C31(-18.348,1.3) C32(-19.066,2.032) C33(-19.729,1.3) C34(-20.292,1.626) C35(-20.855,1.3) C36(-21.573,2.032) C37(-22.236,1.3) C38(-22.8,1.626) C39(-23.363,1.3) C40(-24.081,2.032) C41(-24.744,1.3) C42(-25.307,1.626) C43(-25.87,1.3) C44(-26.588,2.032) C45(-27.251,1.3) C46(-27.815,1.626) C47(-28.378,1.3) C48(-29.07,2.032) C49(-29.759,1.3) C50(-30.322,1.626) C51(-30.885,1.3) C52(-31.578,1.991) C53(-32.266,1.3) C54(-32.83,1.626) C55(-33.393,1.3) C56(-34.085,1.991) C57(-34.774,1.3) C58(-35.337,1.626) C59(-35.9,1.3) C61(-37.003,1.237) D2(-0.65,2.075) D3(-1.3,2.037) D5(-2.678,1.842) D6(-3.369,1.786) D8(-4.157,1.786) D9(-4.944,1.786) D11(-5.852,1.786) D12(-6.735,1.786) D14(-7.522,1.786) D15(-8.43,1.786) D17(-9.313,1.786) D18(-10.1,1.786) D20(-11.008,1.786) D21(-12.235,2.423) D23(-13.377,1.786) D25(-14.714,1.951) D26(-15.277,2.276) D27(-15.84,1.951) D29(-17.221,1.951) D30(-17.785,2.276) D31(-18.348,1.951) D33(-19.729,1.951) D34(-20.292,2.276) D35(-20.855,1.951) D37(-22.236,1.951) D38(-22.8,2.276) D39(-23.363,1.951) D41(-24.744,1.951) D42(-25.307,2.276) D43(-25.87,1.951) D45(-27.251,1.951) D46(-27.815,2.276) D47(-28.378,1.951) D49(-29.759,1.951) D50(-30.322,2.276) D51(-30.885,1.951) D53(-32.266,1.951) D54(-32.83,2.276) D55(-33.393,1.951) D57(-34.774,1.951) D58(-35.337,2.276) D59(-35.9,1.951) D60(-36.678,1.801) D61(-37.328,1.801) D62(-37.978,2.035) E2(-0.65,2.725) E3(-1.3,2.687) E4(-1.951,2.687) E5(-2.602,2.619) E6(-3.554,2.619) E8(-4.507,2.619) E10(-5.459,2.619) E11(-6.412,2.619) E13(-7.364,2.619) E15(-8.317,2.619) E17(-9.269,2.619) E18(-10.222,2.619) E20(-11.174,2.619) E59(-36.027,2.647) E60(-36.678,2.647) E61(-37.328,2.647) E62(-37.978,2.685) F2(-0.65,3.474) F3(-1.3,3.512) F4(-1.951,3.512) F5(-2.602,3.269) F6(-3.554,3.269) F8(-4.507,3.269) F10(-5.459,3.269) F11(-6.412,3.269) F13(-7.364,3.269) F15(-8.317,3.269) F17(-9.269,3.269) F18(-10.222,3.269) F20(-11.174,3.269) F59(-36.027,3.472) F60(-36.678,3.472) F61(-37.328,3.472) F62(-37.978,3.434) F63(-38.628,3.434) G1(0,4.224) G2(-0.65,4.224) G3(-1.3,4.185) G4(-1.951,4.185) G5(-2.602,3.919) G6(-3.554,3.919) G8(-4.507,3.919) G10(-5.459,3.919) G11(-6.412,3.919) G13(-7.364,3.919) G15(-8.317,3.919) G17(-9.269,3.919) G18(-10.222,3.919) G20(-11.174,3.919) H5(-2.602,4.569) H6(-3.554,4.569) H8(-4.507,4.569) H10(-5.459,4.569) H11(-6.412,4.569) H13(-7.364,4.569) H15(-8.317,4.569) H17(-9.269,4.569) H18(-10.222,4.569) H20(-11.174,4.569) H59(-36.027,4.145) H60(-36.678,4.145) H61(-37.328,4.145) H62(-37.978,4.183) H63(-38.628,4.183) J1(0,4.973) J2(-0.65,4.973) J3(-1.3,5.011) J4(-1.951,5.011) J5(-2.627,5.22) J6(-3.567,5.22) J8(-4.507,5.22) J10(-5.459,5.22) J11(-6.412,5.22) J13(-7.364,5.22) J15(-8.317,5.22) J17(-9.269,5.22) J18(-10.222,5.22) J20(-11.174,5.22) J21(-12.095,4.986) J59(-36.027,4.971) J60(-36.678,4.971) J61(-37.328,4.971) J62(-37.978,4.933) J63(-38.628,4.933) K1(0,5.722) K2(-0.65,5.722) K3(-1.3,5.684) K4(-1.951,5.684) K59(-36.027,5.644) K60(-36.678,5.644) K61(-37.328,5.644) K62(-37.978,5.682) K63(-38.628,5.682) L1(0,6.471) L2(-0.65,6.471) L3(-1.3,6.51) L4(-1.951,6.51) L5(-2.637,6.338) L6(-3.287,6.338) L7(-3.937,6.338) L8(-4.587,6.338) L59(-36.027,6.469) L60(-36.678,6.469) L61(-37.328,6.469) L62(-37.978,6.431) L63(-38.628,6.431) N1(0,7.221) N2(-0.65,7.221) N3(-1.3,7.183) N4(-1.951,7.183) N5(-2.637,7.29) N6(-3.287,7.29) N7(-3.937,7.29) N8(-4.587,7.29) N59(-36.027,7.142) N60(-36.678,7.142) N61(-37.328,7.142) N62(-37.978,7.181) N63(-38.628,7.181) P1(0,7.97) P2(-0.65,7.97) P3(-1.3,8.008) P4(-1.951,8.008) P59(-36.027,7.968) P60(-36.678,7.968) P61(-37.328,7.968) P62(-37.978,7.93) P63(-38.628,7.93) R5(-2.637,8.243) R6(-3.287,8.243) R7(-3.937,8.243) R8(-4.587,8.243) T1(0,8.719) T2(-0.65,8.719) T3(-1.3,8.681) T4(-1.951,8.681) T59(-36.027,8.641) T60(-36.678,8.641) T61(-37.328,8.641) T62(-37.978,8.679) T63(-38.628,8.679) U1(0,9.469) U2(-0.65,9.469) U3(-1.3,9.507) U4(-1.951,9.507) U5(-2.637,9.195) U6(-3.287,9.195) U7(-3.937,9.195) U8(-4.587,9.195) U59(-36.027,9.467) U60(-36.678,9.467) U61(-37.328,9.467) U62(-37.978,9.428) U63(-38.628,9.428) V1(0,10.218) V2(-0.65,10.218) V3(-1.3,10.18) V4(-1.951,10.18) V5(-2.637,10.148) V6(-3.287,10.148) V7(-3.937,10.148) V8(-4.587,10.148) V59(-36.027,10.14) V60(-36.678,10.14) V61(-37.328,10.14) V62(-37.978,10.178) V63(-38.628,10.178) Y1(0,10.967) Y2(-0.65,10.967) Y3(-1.3,11.005) Y4(-1.951,11.005) Y5(-2.637,11.1) Y6(-3.287,11.1) Y7(-3.937,11.1) Y8(-4.587,11.1) Y59(-36.027,10.965) Y60(-36.678,10.965) Y61(-37.328,10.965) Y62(-37.978,10.927) Y63(-38.628,10.927)
  round 0.33 smd: AK22(-12.655,16.266) AK23(-13.529,16.266) AK25(-14.504,16.266) AK26(-15.456,16.266) AK28(-16.409,16.266) AK29(-17.311,16.266) AK32(-18.824,16.266) AK33(-19.726,16.266) AK35(-20.729,16.266) AK36(-21.58,16.266) AK38(-22.609,16.266) AK40(-24.106,16.266) AK42(-24.944,16.266) AK43(-25.897,16.266) AK45(-26.874,16.266) AK46(-27.776,16.266) AK48(-28.83,16.266) AK49(-29.732,16.266) AK51(-30.735,16.266) AK52(-31.583,16.266) AK54(-32.61,16.266) AK55(-33.562,16.266) AK57(-34.509,16.266) AK58(-35.408,16.266)
